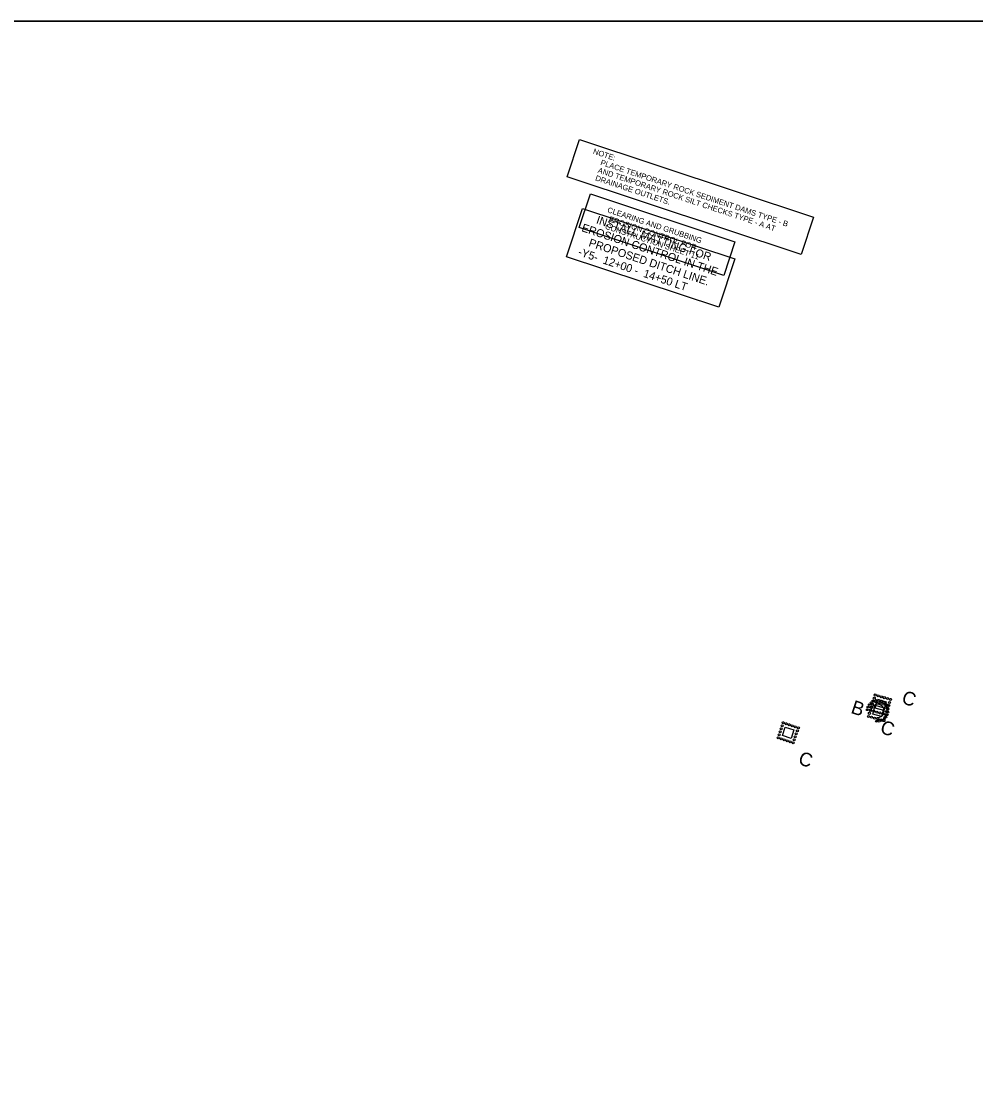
# Model space of a CAD drawing. Extents: x 2470000 to 2520000, y 340000 to 380000.
# Drawn here: x 2481890 to 2482937, y 368831 to 370000 of the extents above; entities that cross this region are included whole.
import ezdxf

# ---------------------------------------------------------------- set-up
doc = ezdxf.new("R2010")
doc.units = 0
for name, color, linetype in [('Construction Sheet Number Note CG CELL', 7, 'Continuous'), ('Label B CG CELL', 7, 'Continuous'), ('Matting in Proposed Ditchline Note Final CELL', 7, 'Continuous'), ('Prop Guardrail', 7, 'Continuous'), ('Prop Guardrail Anchor Unit CELL', 7, 'Continuous'), ('Prop Structure Anchor Unit CELL', 7, 'Continuous'), ('Rock Pipe Inlet Sediment Trap Type B CG CELL', 7, 'Continuous'), ('Scratch_Level_5', 7, 'Continuous'), ('Scratch_Level_6', 7, 'Continuous'), ('Sediment Dams and Silt Check Note CG CELL', 7, 'Continuous')]:
    doc.layers.add(name, color=color, linetype=linetype)

# ---------------------------------------------------------------- blocks, each defined once
blk = doc.blocks.new('C3')
at = {"layer": 'Prop Guardrail'}
blk.add_text('C', height=0.3, dxfattribs=at).set_placement((-0.161, -0.136))
blk = doc.blocks.new('C2')
at = {"layer": 'Prop Guardrail Anchor Unit CELL'}
blk.add_text('C', height=0.3, dxfattribs=at).set_placement((-0.161, -0.136))
blk = doc.blocks.new('B1')
at = {"layer": 'Label B CG CELL'}
blk.add_text('B', height=0.3, dxfattribs=at).set_placement((-0.106, -0.151))
blk = doc.blocks.new('CGNT2')
at = {"layer": 'Sediment Dams and Silt Check Note CG CELL'}
blk.add_lwpolyline([(-2.704, 0.431), (2.704, 0.43125), (2.704, -0.43), (-2.704, -0.43)], close=True, dxfattribs=at)
for s, p in [('NOTE:', (-2.335, 0.231)), ('     PLACE TEMPORARY ROCK SEDIMENT DAMS TYPE - B', (-2.335, 0.05125)), ('     AND TEMPORARY ROCK SILT CHECKS TYPE - A AT', (-2.335, -0.129)), ('     DRAINAGE OUTLETS.', (-2.335, -0.309))]:
    blk.add_text(s, height=0.12, dxfattribs=at).set_placement(p)

msp = doc.modelspace()

# ---------------------------------------------------------------- linework, layer by layer
at = {"layer": 'Construction Sheet Number Note CG CELL'}
msp.add_lwpolyline([(2482514, 369810.6), (2482672.4, 369758), (2482660.1, 369721), (2482501.7, 369773.6)], close=True, dxfattribs=at)
at = {"layer": 'Matting in Proposed Ditchline Note Final CELL'}
msp.add_lwpolyline([(2482505.3, 369794.7), (2482672.4, 369739.3), (2482654.8, 369686.3), (2482487.8, 369741.7)], close=True, dxfattribs=at)
at = {"layer": 'Prop Structure Anchor Unit CELL'}
msp.add_lwpolyline([(2482727.7, 369225.6), (2482737.2, 369222.5), (2482734.1, 369213), (2482724.6, 369216.2)], close=True, dxfattribs=at)
for centre in [(2482725.3, 369230.4), (2482728.7, 369229.3), (2482732, 369228.2), (2482720.9, 369217.1), (2482722, 369220.4), (2482723.1, 369223.8), (2482724.2, 369227.1), (2482735.3, 369227.1), (2482738.6, 369226), (2482739.7, 369218.2), (2482740.9, 369221.6), (2482742, 369224.9), (2482719.8, 369213.8), (2482723.1, 369212.7), (2482726.5, 369211.6), (2482729.8, 369210.5), (2482733.1, 369209.4), (2482736.4, 369208.3), (2482737.5, 369211.6), (2482738.6, 369214.9)]:
    msp.add_circle(centre, 1.12, dxfattribs=at)
at = {"layer": 'Rock Pipe Inlet Sediment Trap Type B CG CELL'}
for centre in [(2482821.8, 369252.3), (2482824.4, 369253.9), (2482827.2, 369254.7), (2482830.2, 369254.7), (2482833.1, 369254), (2482835.7, 369252.6), (2482817.6, 369244.7), (2482818.3, 369247.6), (2482819.8, 369250.2), (2482837.9, 369250.5), (2482839.4, 369247.9), (2482840.2, 369245.1), (2482840.3, 369242.1), (2482827.6, 369232), (2482830.6, 369232.1), (2482833.5, 369232.9), (2482836, 369234.4), (2482838.1, 369236.6), (2482839.6, 369239.2)]:
    msp.add_circle(centre, 1.01, dxfattribs=at)
msp.add_arc((2482828.9, 369243.4), 7.26, 263.5126, 173.5038, dxfattribs=at)
at = {"layer": 'Scratch_Level_5'}
for points in [[(2482828.8, 369256.1), (2482838.4, 369253.4), (2482835.7, 369243.8), (2482826.1, 369246.5)], [(2482826.2, 369249.5), (2482835.9, 369246.9), (2482833.2, 369237.3), (2482823.6, 369239.9)]]:
    msp.add_lwpolyline(points, close=True, dxfattribs=at)
for centre in [(2482823.6, 369254.2), (2482824.3, 369254), (2482825.3, 369257.4), (2482826.2, 369260.8), (2482827, 369253.2), (2482829.6, 369259.8), (2482830.3, 369252.3), (2482833, 369258.9), (2482833.7, 369251.4), (2482836.3, 369257.9), (2482839.7, 369256.9), (2482842.1, 369252.6), (2482843.1, 369256), (2482819.9, 369240.7), (2482820.8, 369244), (2482821.4, 369243.9), (2482821.7, 369247.4), (2482822.4, 369247.3), (2482822.7, 369250.8), (2482823.4, 369250.7), (2482824.8, 369243), (2482828.2, 369242), (2482831.5, 369241.1), (2482834.9, 369240.1), (2482837.1, 369250.5), (2482837.7, 369239.4), (2482838.6, 369242.8), (2482839.2, 369242.5), (2482839.5, 369246.2), (2482840.2, 369245.9), (2482840.5, 369249.6), (2482841.1, 369249.2), (2482819, 369237.3), (2482822.3, 369236.4), (2482825.7, 369235.4), (2482829.1, 369234.5), (2482832.5, 369233.6), (2482835.9, 369232.7), (2482836.8, 369236.1), (2482838.3, 369239.1)]:
    msp.add_circle(centre, 1.12, dxfattribs=at)
at = {"layer": 'Scratch_Level_6'}
for points in [[(2480000, 370000), (2490000, 370000), (2490000, 380000), (2480000, 380000)], [(2480000, 360000), (2490000, 360000), (2490000, 370000), (2480000, 370000)]]:
    msp.add_lwpolyline(points, close=True, dxfattribs=at)

# ---------------------------------------------------------------- block references
at = {"layer": 'Label B CG CELL', "xscale": 49.99999999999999, "yscale": 50, "rotation": -18.37550694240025}
msp.add_blockref('B1', (2482806.1, 369246.8), dxfattribs=at)
at = {"layer": 'Prop Structure Anchor Unit CELL', "xscale": 50, "yscale": 50.00000000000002, "rotation": -18.38982551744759}
msp.add_blockref('C2', (2482750.7, 369189.2), dxfattribs=at)
at = {"layer": 'Scratch_Level_5', "xscale": 50, "yscale": 50, "rotation": -18.361190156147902}
for p in [(2482864.1, 369256), (2482840.5, 369223.4)]:
    msp.add_blockref('C3', p, dxfattribs=at)
at = {"layer": 'Sediment Dams and Silt Check Note CG CELL', "xscale": 50.000000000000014, "yscale": 50.000000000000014, "rotation": -18.375506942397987}
msp.add_blockref('CGNT2', (2482623.4, 369807.1), dxfattribs=at)

# ---------------------------------------------------------------- texts
at = {"layer": 'Construction Sheet Number Note CG CELL'}
for s, p in [('CLEARING AND GRUBBING', (2482531.9, 369790.6)), ('EROSION CONTROL FOR', (2482533.5, 369780.6)), ('CONSTRUCTION SHEET 11', (2482529.5, 369772.5))]:
    msp.add_text(s, height=6, rotation=341.6388, dxfattribs=at).set_placement(p)
at = {"layer": 'Matting in Proposed Ditchline Note Final CELL'}
for s, p in [('INSTALL MATTING FOR ', (2482519.6, 369778.5)), ('EROSION CONTROL IN THE', (2482503.5, 369769.9)), ('PROPOSED DITCH LINE.', (2482511.3, 369753.5)), ('-Y5-  12+00 -  14+50 LT', (2482499.6, 369743.5))]:
    msp.add_text(s, height=8.785, rotation=341.6388, dxfattribs=at).set_placement(p)

doc.saveas('drawing.dxf')
